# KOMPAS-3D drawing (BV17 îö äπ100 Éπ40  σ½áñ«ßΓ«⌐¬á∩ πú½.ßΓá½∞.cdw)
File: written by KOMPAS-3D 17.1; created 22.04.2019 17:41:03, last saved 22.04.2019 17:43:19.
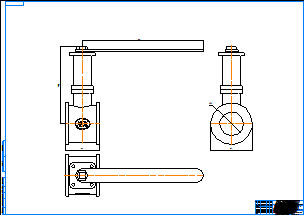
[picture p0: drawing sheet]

Sheet 1: A0, landscape

Title block, sheet 1: name: BV17 МФ Ду100 Ру40 / хладостойкая угл.сталь; material: Внимание! Данный продукт является объектом авторского права ООО «Торговый Дом АДЛ». / Запрещается изменение, копирование, распространение / (в том числе путем копирования на другие сайты и ресурсы в Интернете) / или любое иное использование информации и объектов без предварительного / согласия правообладателя (ООО «Торговый Дом АДЛ»).; mass: 20,89; sheets: 1; organisation: ООО "Торговый дом АДЛ"; sheet format: A0; stored path: \\adlc.lan\data\АДЛ_ПКД\3D-модели\ADL production\Краны шаровые серии BV\BV17 МФ хладостойкая угл.сталь Ру40\KOMPAS 2D\BV17 МФ Ду100 Ру40  хладостойкая угл.сталь.cdw

Views: Вид 1, Проекционный вид 3, Проекционный вид 4
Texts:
  user
Dimensions and other numbers on the sheet: 472; 304; 135; 164; 94; 1:1; 1; 20,89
